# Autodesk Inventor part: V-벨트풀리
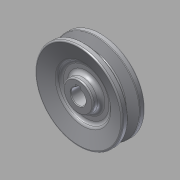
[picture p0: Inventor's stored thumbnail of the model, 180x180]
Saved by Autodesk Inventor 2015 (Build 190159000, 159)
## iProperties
Created: 2016-08
Part Number: V-벨트풀리
Material: 알루미늄 6061
Document SubType Name: Modeling
Designer: mduedu
Density: 2.71 g/cm^3
Appearance: 알루미늄 - 평지
Mass: 101.313 g
Surface Area: 152.704 cm^2
Volume: 37.3847 cm^3
Author: mduedu
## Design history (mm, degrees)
sketch "스케치1"
  geometry: L1 (0, 9.5)-(0, -9.5); L2 (0, 9.5)-(35, 9.5); L3 (35, 9.5)-(35, 4.825); L4 (35, 4.825)-(26, 2.074); L5 (26, 2.074)-(26, 0); L6 (0, 0)-(26, 0); L7 (0, -9.5)-(35, -9.5); L8 (35, -9.5)-(35, -4.825); L9 (35, -4.825)-(26, -2.074); L10 (26, -2.074)-(26, 0); L11 (32.3, 9.5)-(32.3, -9.5); 3 further points
  constraints: 22 end point, 6 point on line, 4 perpendicular, 3 symmetric about line, 1 coincident, 1 horizontal alignment, 1 midpoint, 1 parallel, 1 vertical
  dimensions: "d0" = 19 distance of L1.start L1.end; "d2" = 70 diameter of L8 L1; "d4" = 6.3 distance between parallel lines of L10 L11; "d5" = 2.7 distance between parallel lines of L11 L8; "d6" = 8 distance of point (32.3, -4) point (32.3, 4); "d7" = 34 deg angle of L9 L4
revolve "회전1" sketch "스케치1" stored, may be unused: angle "d8" = 90 deg
sketch "스케치2"
  geometry: L1 (-2, 0)-(2, 0); L2 (2, 0)-(2, 7.8); L3 (2, 7.8)-(-2, 7.8); L4 (-2, 7.8)-(-2, 0); C1 r 6 at (0, 0); 2 further points
  constraints: 8 end point, 2 coincident, 2 parallel, 1 centre point, 1 horizontal, 1 midpoint, 1 perpendicular
  dimensions: "d9" = 12 diameter of C1; "d11" = 4 distance of L2.end L3.end; "d12" = 7.8 distance of L1.end L2.end
extrude "돌출1" cut sketch "스케치2" stored distance "d13" = 10; taper "d14" = 0 deg
sketch "스케치3"
  geometry: L1 (35, 4.825)-(26, 2.074) reference; L2 (26, 2.074)-(26, -2.074) reference; L3 (0, 0)-(26, 0); L4 (35, 9.5)-(35, 4.825) reference; L5 (-35, 9.5)-(35, 9.5) reference; L6 (35, 9.5)-(21, 5.22); L7 (21, 5.22)-(21, 3); L8 (21, 3)-(12, 3); L9 (12, 3)-(12, 9.5); L10 (0, 9.5)-(0, -9.5); L11 (5.657, -9.5)-(-6, -9.5) reference; L12 (12, 9.5)-(35, 9.5)
  constraints: 14 end point, 3 midpoint, 2 parallel, 2 perpendicular, 2 point on line, 1 collinear, 1 horizontal
  dimensions: "d15" = 3 distance between parallel lines of L3 L8; "d17" = 42 diameter of L7 L10; "d18" = 24 diameter of L9 L10
revolve "회전2" sketch "스케치3" stored, may be unused: angle "d19" = 90 deg
fillet "모깎기1" dims "d20" = 0.5, "d21" = 1, "d22" = 1
fillet "모깎기2" dims "d23" = 3
fillet "모깎기3" dims "d24" = 3
fillet "모깎기4" dims "d25" = 3
chamfer "모따기1" distance "d26" = 0.5; stored, may be unused: second distance "d27" = 2, angle "d28" = 45 deg
fillet "모깎기5" dims "d29" = 1
node "솔리드1"
mirror "대칭1"
